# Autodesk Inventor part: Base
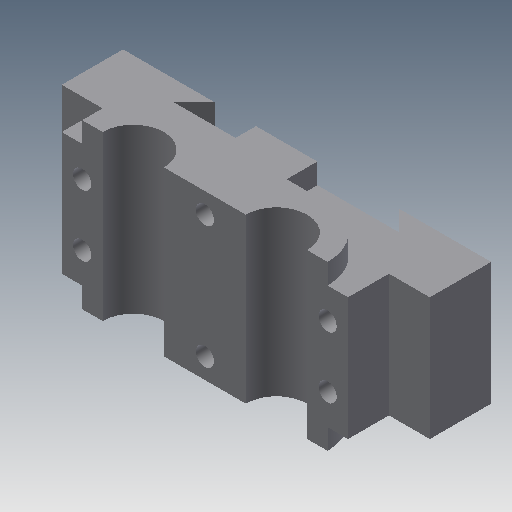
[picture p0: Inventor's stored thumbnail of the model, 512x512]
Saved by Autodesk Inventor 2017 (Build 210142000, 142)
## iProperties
Shininess: 77.0
Length Units: 11269
Angle Units: 11279
Time Units: 11290
Mass Units: 11283
Length Display Precision: 3
Angle Display Precision: 2
Created: 2002-02
Part Number: Base
Document SubType Name: Modeling
Designer: ***
Density: 1 g/cm^3
Material: Generic
Appearance: Default
Density: 0.0
Volumn: 0.0
Area: 0.0
PropertySet Name: Model Information
Control State: 0
Master: False
Checked Out: False
Author: ***
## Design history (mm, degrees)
sketch "Sketch2"
  geometry: L1 (-10.066, -1.263)-(24.934, -1.263); L2 (37.434, 11.237)-(32.434, 11.237); L3 (17.434, 11.237)-(-2.566, 11.237); L4 (-17.566, 11.237)-(-22.566, 11.237); A1 r 12.5 centre (-10.066, 11.237) between (-22.566, 11.237) and (-10.066, -1.263); A2 r 12.5 centre (24.934, 11.237) between (24.934, -1.263) and (37.434, 11.237); A3 r 7.5 centre (24.934, 11.237) between (17.434, 11.237) and (32.434, 11.237); A4 r 7.5 centre (-10.066, 11.237) between (-17.566, 11.237) and (-2.566, 11.237)
  constraints: 8 end point, 8 point on circle, 4 centre point, 3 horizontal, 3 parallel, 2 coincident, 2 equal radius, 2 tangent
  dimensions: "d0" = 12.5 radius of A1; "d1" = 7.5 radius of A4; "d2" = 35 distance of A1.centre A2.centre; "d3" = 12.5 distance between parallel lines of L3 L1
extrude "Extrusion1" new body sketch "Sketch2" stored distance "d4" = 40; taper "d5" = 0 deg
sketch "Sketch4"
  geometry: L1 (-27.566, 1.237)-(-37.566, 1.237); L2 (-37.566, 1.237)-(-37.566, -13.763); L3 (-37.566, -13.763)-(-15.066, -13.763); L4 (-15.066, -13.763)-(-20.066, -8.763); L5 (-20.066, -8.763)-(34.934, -8.763); L6 (34.934, -8.763)-(29.934, -13.763); L7 (29.934, -13.763)-(52.434, -13.763); L8 (52.434, -13.763)-(52.434, 1.237); L9 (52.434, 1.237)-(42.434, 1.237); L10 (24.934, -1.263)-(-10.066, -1.263); L11 (-17.566, 11.237)-(-22.566, 11.237) reference; L12 (37.434, 11.237)-(32.434, 11.237) reference; L13 (-22.566, 11.237)-(-27.566, 11.237); L14 (-27.566, 11.237)-(-27.566, 1.237); L15 (37.434, 11.237)-(42.434, 11.237); L16 (42.434, 11.237)-(42.434, 1.237); A1 r 12.5 centre (24.934, 11.237) between (24.934, -1.263) and (37.434, 11.237); A2 r 12.5 centre (-10.066, 11.237) between (-22.566, 11.237) and (-10.066, -1.263); A3 r 12.5 centre (24.934, 11.237) between (24.934, -1.263) and (37.434, 11.237) reference; A4 r 12.5 centre (-10.066, 11.237) between (-22.566, 11.237) and (-10.066, -1.263) reference
  constraints: 28 end point, 6 perpendicular, 5 equal length, 4 concentric, 4 parallel, 4 point on circle, 2 centre point, 2 collinear, 1 tangent
  dimensions: "d12" = 15 distance of L1.end L2.end; "d13" = 25 distance from line of L3 L11.end; "d14" = 90 distance between parallel lines of L2 L8; "d15" = 5 distance between parallel lines of L5 L7; "d16" = 22.5 distance of L2.end L3.end; "d24" = 5 distance of L12.start L15.end; "d25" = 15 distance from line of L8 L12.start
extrude "Extrusion3" join sketch "Sketch4" stored distance "d17" = 30; taper "d18" = 0 deg
sketch "Sketch5"
  geometry: L1 (-14.934, -1.263)-(0.066, -1.263); L2 (0.066, -1.263)-(0.066, -8.763); L3 (0.066, -8.763)-(-14.934, -8.763); L4 (-14.934, -8.763)-(-14.934, -1.263); L5 (10.066, -1.263)-(-24.934, -1.263) reference; 1 further point
  constraints: 8 end point, 2 parallel, 1 collinear, 1 horizontal, 1 perpendicular
  dimensions: "d19" = 7.5 distance of L1.end L2.end; "d20" = 15 distance of L2.end L3.end; "d21" = 15 distance from line of point (-29.934, -13.763) L4
extrude "Extrusion4" join sketch "Sketch5" distance "d22" = 40; taper "d23" = 0 deg
sketch "Sketch6"
  geometry: L1 (-5, -35)-(0, -35) reference; L2 (-5, -35)-(-5, -5) reference; 1 further point
  dimensions: "d26" = 7.5 distance from line of L1 point (0, -27.5); "d27" = 5 distance from line of L2 point (0, -27.5)
hole "Hole1" sketch "Sketch6" at (0, -27.5) diameter "d28" = 4.5; stored, may be unused: countersink angle "d32" = 82 deg, drill point angle "d34" = 0 deg; dims "d29" = 6, "d30" = 4, "d31" = 2, "d33" = 15
pattern_linear "Rectangular Pattern1" dims "d37" = 60, "d40" = 15
sketch "Sketch7"
  geometry: L1 (-20, -40)-(-20, -35) reference; L2 (0, -40)-(20, -40) reference; 1 further point
  dimensions: "d41" = 30 distance from line of L1 point (10, -35); "d42" = 5 distance from line of L2 point (10, -35)
hole "Hole2" sketch "Sketch7" at (10, -35) diameter "d43" = 4.5; stored, may be unused: countersink angle "d47" = 82 deg, drill point angle "d49" = 0 deg; dims "d44" = 6, "d45" = 4, "d46" = 2, "d48" = 15
pattern_linear "Rectangular Pattern2" dims "d52" = 30
body "Solid1"
